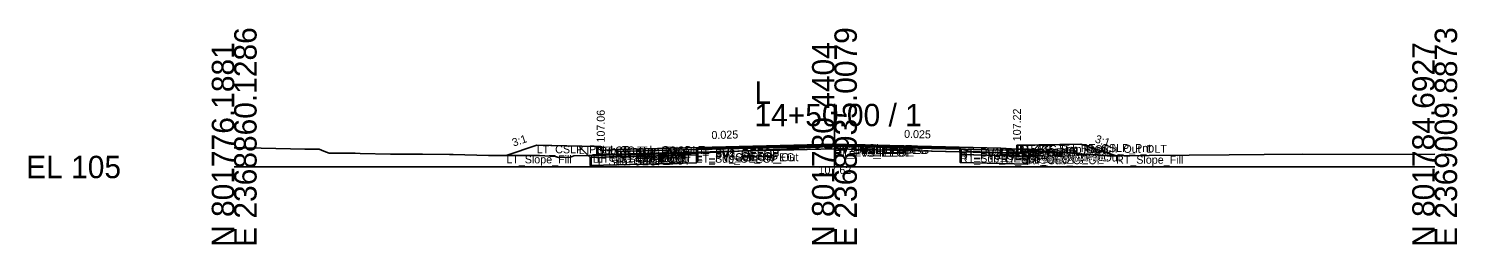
# Model space of a CAD drawing. Extents: x -26 to 8153, y -10 to 9520.
# Drawn here: x -25.7 to 152.8, y 5490.3 to 5517.3 of the extents above; entities that cross this region are included whole.
import ezdxf

# ---------------------------------------------------------------- set-up
doc = ezdxf.new("R2010")
doc.units = 0
for name, color, linetype in [('Exist CMT Pavement', 7, 'Continuous'), ('Exist Cross Section Cell', 7, 'Continuous'), ('Exist XS Center Line Elevation Label', 7, 'Continuous'), ('Exist XS Ground Line', 7, 'Continuous'), ('Prop CMT Conc Surface', 7, 'Continuous'), ('Prop CMT Concrete Structures', 7, 'Continuous'), ('Prop CMT Pvmt Course 1', 7, 'Continuous'), ('Prop CMT Pvmt Course 1 CG', 7, 'Continuous'), ('Prop CMT Pvmt Course 1 Wedge', 7, 'Continuous'), ('Prop CMT Pvmt Course 2', 7, 'Continuous'), ('Prop CMT Pvmt Course 2 Wedge', 7, 'Continuous'), ('Prop CMT Pvmt Course 3', 7, 'Continuous'), ('Prop CMT Pvmt Course 3 Wedge', 7, 'Continuous'), ('Prop CMT Pvmt Surface', 7, 'Continuous'), ('Prop CMT Pvmt Wedge Surface 1', 7, 'Continuous'), ('Prop CMT Pvmt Wedge Surface 2', 7, 'Continuous'), ('Prop CMT Pvmt Wedge Surface 3', 7, 'Continuous'), ('Prop CMT Shallow Undercut', 7, 'Continuous'), ('Prop CMT Shallow Undercut Boundary', 7, 'Continuous'), ('Prop CMT Slope Grass', 7, 'Continuous'), ('Prop CMT Subgrade Earthwork', 7, 'Continuous'), ('Prop XS Earthwork Shape', 7, 'Continuous'), ('Prop XS Hydro Elevations', 7, 'Continuous'), ('Prop XS SE Text', 7, 'Continuous'), ('Prop XS Side Slope Text', 7, 'Continuous'), ('Prop XS Subgrade Earthwork', 7, 'Continuous'), ('Scratch_Level_2', 7, 'Continuous'), ('Scratch_Level_6', 7, 'Continuous')]:
    doc.layers.add(name, color=color, linetype=linetype)

msp = doc.modelspace()

# ---------------------------------------------------------------- linework, layer by layer
at = {"layer": 'Exist CMT Pavement'}
for p, q in [((68.29, 5502.24), (75, 5502.62)), ((75, 5502.62), (75.31, 5502.63)), ((75.31, 5502.63), (81.26, 5502.52)), ((81.26, 5502.52), (90.69, 5502.28)), ((57.77, 5501.72), (60.32, 5501.87)), ((60.32, 5501.87), (68.29, 5502.24))]:
    msp.add_line(p, q, dxfattribs=at)
at = {"layer": 'Exist Cross Section Cell'}
for p, q in [((75, 5500), (75, 5507.9)), ((0, 5500), (75, 5500)), ((75, 5500), (150, 5500))]:
    msp.add_line(p, q, dxfattribs=at)
at = {"layer": 'Exist XS Ground Line'}
for p, q in [((0, 5502.39), (1.53, 5502.38)), ((1.53, 5502.38), (7.04, 5502.26)), ((68.29, 5502.24), (75, 5502.62)), ((75, 5502.62), (75.31, 5502.63)), ((75.31, 5502.63), (81.26, 5502.52)), ((81.26, 5502.52), (90.69, 5502.28)), ((7.04, 5502.26), (8.84, 5502.23)), ((8.84, 5502.23), (10.62, 5502.22)), ((10.62, 5502.22), (11.18, 5501.99)), ((11.18, 5501.99), (11.85, 5501.72)), ((11.85, 5501.72), (14.51, 5501.72)), ((14.51, 5501.72), (15.13, 5501.71)), ((15.13, 5501.71), (15.74, 5501.7)), ((15.74, 5501.7), (19.53, 5501.62)), ((19.53, 5501.62), (23.14, 5501.61)), ((23.14, 5501.61), (23.53, 5501.61)), ((23.53, 5501.61), (26.91, 5501.55)), ((26.91, 5501.55), (27.35, 5501.55)), ((27.35, 5501.55), (31.76, 5501.45)), ((31.76, 5501.45), (32.18, 5501.45)), ((32.18, 5501.45), (37.26, 5501.44)), ((37.26, 5501.44), (37.63, 5501.44)), ((37.63, 5501.44), (38.13, 5501.42)), ((38.13, 5501.42), (40.14, 5501.3)), ((40.14, 5501.3), (40.51, 5501.2)), ((40.51, 5501.2), (42.02, 5501.23)), ((42.02, 5501.23), (42.42, 5501.38)), ((42.42, 5501.38), (52.17, 5501.59)), ((52.17, 5501.59), (57.77, 5501.72)), ((57.77, 5501.72), (60.32, 5501.87)), ((60.32, 5501.87), (68.29, 5502.24)), ((90.69, 5502.28), (91.98, 5501.94)), ((91.98, 5501.94), (96.79, 5501.75)), ((96.79, 5501.75), (100.06, 5501.96)), ((100.06, 5501.96), (102.38, 5501.88)), ((102.38, 5501.88), (109.06, 5501.39)), ((109.06, 5501.39), (114.31, 5501.45)), ((114.31, 5501.45), (124.3, 5501.54)), ((124.3, 5501.54), (128.69, 5501.56)), ((128.69, 5501.56), (133.54, 5501.59)), ((133.54, 5501.59), (147.91, 5501.58)), ((147.91, 5501.58), (150, 5501.59))]:
    msp.add_line(p, q, dxfattribs=at)
at = {"layer": 'Prop CMT Conc Surface'}
for points in [[(45.8, 5502.06), (45.8, 5502.56), (45.3, 5502.56)], [(97.8, 5502.22), (97.8, 5502.72), (98.3, 5502.72)], [(47.8, 5502.19), (45.8, 5502.06)], [(95.8, 5502.35), (97.8, 5502.22)]]:
    msp.add_lwpolyline(points, dxfattribs=at)
at = {"layer": 'Prop CMT Concrete Structures'}
for points in [[(47.8, 5502.19), (45.8, 5502.06), (45.8, 5502.56), (45.3, 5502.56)], [(45.3, 5502.56), (45.3, 5501.54), (47.8, 5501.61)], [(95.8, 5502.35), (97.8, 5502.22), (97.8, 5502.72), (98.3, 5502.72)], [(98.3, 5502.72), (98.3, 5501.7), (95.8, 5501.77)], [(47.8, 5501.61), (47.8, 5502.19)], [(95.8, 5501.77), (95.8, 5502.35)]]:
    msp.add_lwpolyline(points, dxfattribs=at)
at = {"layer": 'Prop CMT Pvmt Course 1'}
for points in [[(75, 5502.87), (47.8, 5502.19)], [(57.77, 5502.31), (75, 5502.75)], [(75, 5502.62), (75, 5502.87)], [(75, 5502.87), (95.8, 5502.35)], [(75, 5502.62), (75, 5502.87)], [(75, 5502.75), (75, 5502.62), (75, 5502.62)], [(90.69, 5502.35), (75, 5502.75)], [(75, 5502.75), (75, 5502.62), (75, 5502.62)], [(47.8, 5502.19), (47.8, 5501.94)], [(47.8, 5501.94), (57.77, 5502.19)], [(57.77, 5502.19), (57.77, 5502.31)], [(90.69, 5502.23), (90.69, 5502.35)], [(95.8, 5502.1), (90.69, 5502.23)], [(95.8, 5502.35), (95.8, 5502.1)]]:
    msp.add_lwpolyline(points, dxfattribs=at)
at = {"layer": 'Prop CMT Pvmt Course 1 CG'}
for points in [[(47.8, 5501.61), (44.8, 5501.53), (44.46, 5501.19)], [(44.46, 5501.19), (47.8, 5501.28)], [(47.8, 5501.28), (47.8, 5501.61)], [(95.8, 5501.77), (98.8, 5501.69), (99.14, 5501.35)], [(95.8, 5501.44), (95.8, 5501.77)], [(99.14, 5501.35), (95.8, 5501.44)]]:
    msp.add_lwpolyline(points, dxfattribs=at)
at = {"layer": 'Prop CMT Pvmt Course 1 Wedge'}
for points in [[(75, 5502.75), (57.77, 5502.31)], [(75, 5502.75), (90.69, 5502.35)]]:
    msp.add_lwpolyline(points, dxfattribs=at)
at = {"layer": 'Prop CMT Pvmt Course 2'}
for points in [[(57.77, 5502.19), (47.8, 5501.94)], [(47.8, 5501.94), (47.8, 5501.61)], [(47.8, 5501.61), (57.77, 5501.86)], [(57.77, 5501.86), (57.77, 5502.19)], [(90.69, 5501.9), (90.69, 5502.23)], [(90.69, 5502.23), (95.8, 5502.1)], [(95.8, 5501.77), (90.69, 5501.9)], [(95.8, 5502.1), (95.8, 5501.77)]]:
    msp.add_lwpolyline(points, dxfattribs=at)
at = {"layer": 'Prop CMT Pvmt Course 2 Wedge'}
for points in [[(75, 5502.62), (57.77, 5502.19)], [(75, 5502.62), (90.69, 5502.23)]]:
    msp.add_lwpolyline(points, dxfattribs=at)
at = {"layer": 'Prop CMT Pvmt Course 3'}
for points in [[(57.77, 5501.86), (47.8, 5501.61)], [(47.8, 5501.61), (47.8, 5501.28)], [(47.8, 5501.28), (57.77, 5501.53)], [(57.77, 5501.53), (57.77, 5501.86)], [(90.69, 5501.9), (95.8, 5501.77)], [(90.69, 5501.57), (90.69, 5501.9)], [(95.8, 5501.44), (90.69, 5501.57)], [(95.8, 5501.77), (95.8, 5501.44)]]:
    msp.add_lwpolyline(points, dxfattribs=at)
at = {"layer": 'Prop CMT Pvmt Course 3 Wedge'}
for points in [[(75, 5502.29), (57.77, 5501.86)], [(75, 5502.29), (90.69, 5501.9)]]:
    msp.add_lwpolyline(points, dxfattribs=at)
at = {"layer": 'Prop CMT Pvmt Surface'}
for points in [[(75, 5502.87), (47.8, 5502.19)], [(75, 5502.87), (95.8, 5502.35)]]:
    msp.add_lwpolyline(points, dxfattribs=at)
at = {"layer": 'Prop CMT Pvmt Wedge Surface 1'}
for points in [[(75, 5502.75), (57.77, 5502.31)], [(75, 5502.75), (90.69, 5502.35)], [(57.77, 5502.19), (47.8, 5501.94)], [(47.8, 5501.94), (47.8, 5502.19)], [(57.77, 5502.31), (57.77, 5502.19)], [(90.69, 5502.35), (90.69, 5502.23)], [(90.69, 5502.23), (95.8, 5502.1)], [(95.8, 5502.1), (95.8, 5502.35)]]:
    msp.add_lwpolyline(points, dxfattribs=at)
at = {"layer": 'Prop CMT Pvmt Wedge Surface 2'}
for points in [[(75, 5502.62), (47.8, 5501.94)], [(75, 5502.62), (95.8, 5502.1)], [(47.8, 5501.94), (47.8, 5502.19)], [(95.8, 5502.1), (95.8, 5502.35)]]:
    msp.add_lwpolyline(points, dxfattribs=at)
at = {"layer": 'Prop CMT Pvmt Wedge Surface 3'}
for points in [[(75, 5502.29), (47.8, 5501.61)], [(47.8, 5501.61), (47.8, 5502.19)], [(75, 5502.29), (95.8, 5501.77)], [(95.8, 5501.77), (95.8, 5502.35)]]:
    msp.add_lwpolyline(points, dxfattribs=at)
at = {"layer": 'Prop CMT Shallow Undercut'}
for p, q in [((57.77, 5501.53), (44.46, 5501.19)), ((99.14, 5501.35), (90.69, 5501.57))]:
    msp.add_line(p, q, dxfattribs=at)
for points in [[(44.46, 5501.19), (44.46, 5500.19), (57.77, 5500.53), (57.77, 5501.53)], [(90.69, 5501.57), (90.69, 5500.57), (99.14, 5500.35), (99.14, 5501.35)]]:
    msp.add_lwpolyline(points, dxfattribs=at)
at = {"layer": 'Prop CMT Shallow Undercut Boundary'}
for p, q in [((44.46, 5501.19), (57.77, 5501.53)), ((44.46, 5501.19), (44.46, 5500.19)), ((57.77, 5500.53), (57.77, 5501.53)), ((90.69, 5501.57), (90.69, 5500.57)), ((90.69, 5501.57), (99.14, 5501.35)), ((99.14, 5500.35), (99.14, 5501.35)), ((44.46, 5500.19), (57.77, 5500.53)), ((90.69, 5500.57), (99.14, 5500.35))]:
    msp.add_line(p, q, dxfattribs=at)
at = {"layer": 'Prop CMT Slope Grass'}
for points in [[(45.3, 5502.56), (37.8, 5502.71), (34, 5501.45)], [(98.3, 5502.72), (105.8, 5502.87), (110.19, 5501.41)]]:
    msp.add_lwpolyline(points, dxfattribs=at)
at = {"layer": 'Prop CMT Subgrade Earthwork'}
for points in [[(47.8, 5501.28), (44.46, 5501.19), (43.05, 5502.61)], [(95.8, 5501.44), (99.14, 5501.35), (100.55, 5502.77)], [(57.77, 5501.53), (47.8, 5501.28)], [(57.77, 5501.53), (57.78, 5501.72)], [(90.69, 5501.57), (90.68, 5502.28)], [(90.69, 5501.57), (95.8, 5501.44)]]:
    msp.add_lwpolyline(points, dxfattribs=at)
at = {"layer": 'Prop XS Earthwork Shape'}
for points in [[(38.13, 5501.42), (40.14, 5501.3), (40.51, 5501.2), (42.02, 5501.23), (42.42, 5501.38), (44.24, 5501.42), (43.05, 5502.61), (37.8, 5502.71), (34, 5501.45), (37.26, 5501.44), (37.63, 5501.44)], [(100.06, 5501.96), (102.38, 5501.88), (109.06, 5501.39), (110.19, 5501.41), (105.8, 5502.87), (100.55, 5502.77), (99.72, 5501.94)], [(44.46, 5501.19), (44.24, 5501.42), (52.17, 5501.59), (57.77, 5501.72), (57.78, 5501.72), (57.77, 5501.53), (47.8, 5501.28)], [(44.46, 5500.19), (57.77, 5500.53), (57.77, 5501.53), (47.8, 5501.28), (44.46, 5501.19)], [(96.79, 5501.75), (99.72, 5501.94), (99.14, 5501.35), (95.8, 5501.44), (90.69, 5501.57), (90.68, 5502.28), (90.69, 5502.28), (91.98, 5501.94)], [(99.14, 5500.35), (99.14, 5501.35), (95.8, 5501.44), (90.69, 5501.57), (90.69, 5500.57)]]:
    msp.add_lwpolyline(points, close=True, dxfattribs=at)
at = {"layer": 'Prop XS Subgrade Earthwork'}
for p, q in [((44.46, 5501.19), (57.77, 5501.53)), ((90.69, 5501.57), (99.14, 5501.35))]:
    msp.add_line(p, q, dxfattribs=at)
at = {"layer": 'Scratch_Level_6'}
for p, q in [((57.77, 5501.53), (44.46, 5501.19)), ((99.14, 5501.35), (90.69, 5501.57))]:
    msp.add_line(p, q, dxfattribs=at)
for points in [[(44.46, 5501.19), (44.46, 5500.19), (57.77, 5500.53), (57.77, 5501.53)], [(90.69, 5501.57), (90.69, 5500.57), (99.14, 5500.35), (99.14, 5501.35)]]:
    msp.add_lwpolyline(points, dxfattribs=at)

# ---------------------------------------------------------------- texts
at = {"layer": 'Exist Cross Section Cell'}
for s, p in [('E 2368860.1286', (2.8, 5490)), ('E 2368935.0079', (77.8, 5490)), ('E 2369009.8873', (152.8, 5490)), ('N 801776.1881', (0, 5490)), ('N 801780.4404', (75, 5490)), ('N 801784.6927', (150, 5490))]:
    msp.add_text(s, height=2.8, rotation=90, dxfattribs=at).set_placement(p)
for s, p in [('L', (65, 5507.9)), ('14+50.00 / 1', (65, 5505.1)), ('EL 105', (-26, 5498.6))]:
    msp.add_text(s, height=2.8, dxfattribs=at).set_placement(p)
at = {"layer": 'Exist XS Center Line Elevation Label'}
msp.add_text('107.62', height=1, dxfattribs=at).set_placement((73.01, 5499.12))
at = {"layer": 'Prop XS Hydro Elevations'}
for s, p in [('107.06', (46.3, 5503.06)), ('107.22', (98.3, 5503.22))]:
    msp.add_text(s, height=1, rotation=90, dxfattribs=at).set_placement(p)
at = {"layer": 'Prop XS SE Text'}
for rotation, p in [(1.4321, (59.64, 5503.49)), (358.5679, (83.69, 5503.65))]:
    msp.add_text('0.025', height=1, rotation=rotation, dxfattribs=at).set_placement(p)
at = {"layer": 'Prop XS Side Slope Text'}
for rotation, p in [(18.4349, (34.91, 5502.54)), (341.5651, (107.48, 5503.1))]:
    msp.add_text('3:1', height=1, rotation=rotation, dxfattribs=at).set_placement(p)
at = {"layer": 'Scratch_Level_2'}
for s, p in [('LT_CSLP_Pnt', (37.8, 5501.71)), ('LT_Sub_Trench_Out_DLT', (43.05, 5501.61)), ('LT_CG_Top_BOC', (45.3, 5501.56)), ('LT_CG_Top_Face', (45.8, 5501.56)), ('PV1_PGL', (75, 5501.87)), ('RT_PV1_IEEOP', (75, 5501.75)), ('LT_PV1_IEEOP', (75, 5501.75)), ('RT_PV2_IEEOP', (75, 5501.62)), ('LT_PV2_IEEOP', (75, 5501.62)), ('PV2_PGL', (75, 5501.62)), ('RT_PV_IEEOP_EG', (75, 5501.62)), ('LT_PV_IEEOP_EG', (75, 5501.62)), ('RT_CG_Top_Face', (97.8, 5501.72)), ('RT_CG_Top_BOC', (98.3, 5501.72)), ('RT_Sub_Trench_Out_DLT', (100.55, 5501.77)), ('RT_CSLP_Pnt', (105.8, 5501.87)), ('LT_Slope_Fill', (34, 5500.45)), ('LT_Sub_OEOP', (44.46, 5500.19)), ('LT_CG1_Shelf_Out', (44.8, 5500.53)), ('LT_CG_Bot_BOC', (45.3, 5500.54)), ('LT_CG_Top_Gut', (45.8, 5501.06)), ('LT_PV1_OEOT', (47.8, 5501.19)), ('LT_PV2_OEOT', (47.8, 5500.94)), ('LT_PV3_OEOT', (47.8, 5500.61)), ('LT_CG_Bot_IE', (47.8, 5500.61)), ('LT_Sub_OEOT', (47.8, 5500.28)), ('LT_PV1_OEEOP', (57.77, 5501.31)), ('LT_PV2_OEEOP', (57.77, 5501.19)), ('LT_PV3_OEEOP', (57.77, 5500.86)), ('LT_PV_OEEOP_EG', (57.77, 5500.72)), ('LT_Sub_OEEOP', (57.77, 5500.53)), ('LT_PV_Sub_Tie_Out', (57.78, 5500.72)), ('RT_PV3_IEEOP', (75, 5501.29)), ('LT_PV3_IEEOP', (75, 5501.29)), ('RT_PV_Sub_Tie_Out', (90.68, 5501.28)), ('RT_PV1_OEEOP', (90.69, 5501.35)), ('RT_PV_OEEOP_EG', (90.69, 5501.28)), ('RT_PV2_OEEOP', (90.69, 5501.23)), ('RT_PV3_OEEOP', (90.69, 5500.9)), ('RT_Sub_OEEOP', (90.69, 5500.57)), ('RT_PV1_OEOT', (95.8, 5501.35)), ('RT_PV2_OEOT', (95.8, 5501.1)), ('RT_PV3_OEOT', (95.8, 5500.77)), ('RT_CG_Bot_IE', (95.8, 5500.77)), ('RT_Sub_OEOT', (95.8, 5500.44)), ('RT_CG_Top_Gut', (97.8, 5501.22)), ('RT_CG_Bot_BOC', (98.3, 5500.7)), ('RT_CG1_Shelf_Out', (98.8, 5500.69)), ('RT_Sub_OEOP', (99.14, 5500.35)), ('RT_Slope_Fill', (110.19, 5500.41))]:
    msp.add_text(s, height=1, dxfattribs=at).set_placement(p)

doc.saveas('drawing.dxf')
